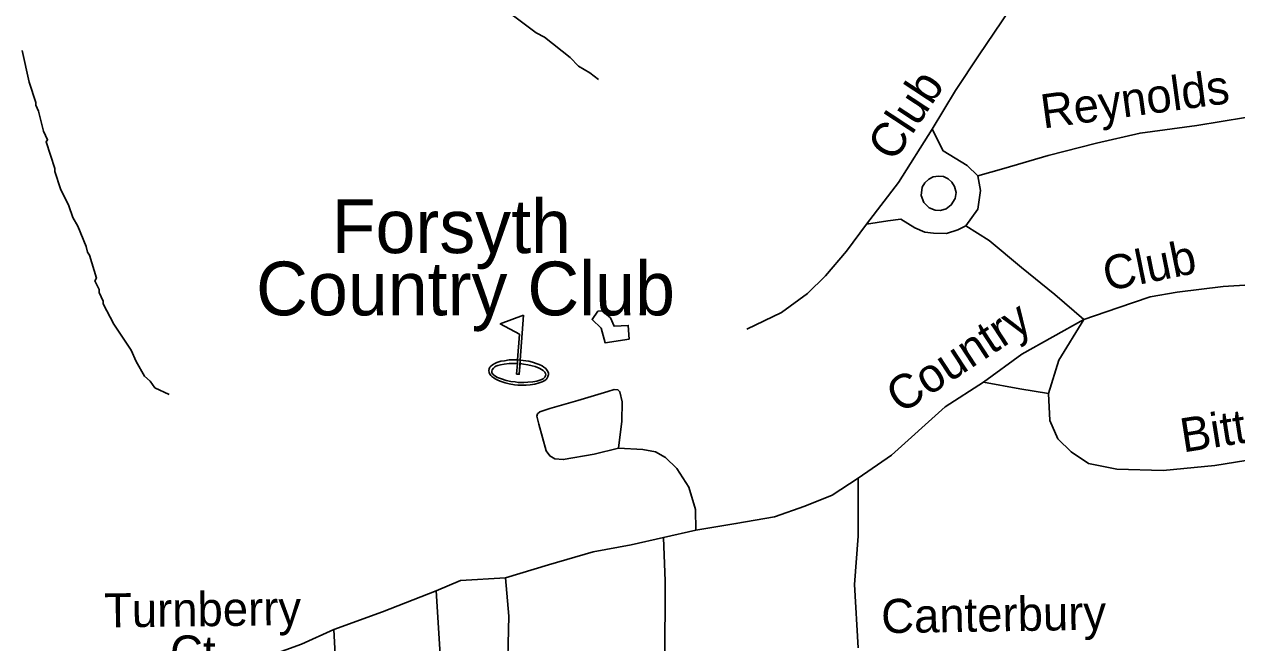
# Model space of a CAD drawing. Extents: x 1547597 to 1699558, y 810033 to 920809.
# Drawn here: x 1614630 to 1618018, y 856716 to 858442 of the extents above; entities that cross this region are included whole.
import ezdxf

# ---------------------------------------------------------------- set-up
doc = ezdxf.new("R2010")
doc.units = 0
for name, color, linetype in [('Exist Cultural Recreational Golf Course CELL', 7, 'Continuous'), ('Exist Cultural Recreational Golf Course Label', 7, 'Continuous'), ('Exist Hydrographic Misc Water Feature', 7, 'Continuous'), ('Exist Road Non-System Type 51', 7, 'Continuous'), ('Exist Road Non-System Type 51 Label', 7, 'Continuous')]:
    doc.layers.add(name, color=color, linetype=linetype)

msp = doc.modelspace()

# ---------------------------------------------------------------- linework, layer by layer
at = {"layer": 'Exist Cultural Recreational Golf Course CELL'}
msp.add_lwpolyline([(1616025.6, 857630), (1615960.2, 857605.4), (1616014.3, 857576.7), (1616009, 857505.3), (1616016.3, 857504.8), (1616015.6, 857494.8), (1616013.4, 857464.9), (1616015.6, 857494.8), (1616025, 857493.5), (1616037.1, 857491.3), (1616049.5, 857488.7), (1616057.8, 857486.4), (1616068.7, 857482.2), (1616071.4, 857481.2), (1616080.1, 857475.8), (1616084.6, 857471.1), (1616086.5, 857467.1), (1616087.4, 857463.2), (1616087.1, 857461.5), (1616086.6, 857459.9), (1616086.1, 857458.6), (1616085.1, 857457.2), (1616080.5, 857452.7), (1616073.9, 857449.4), (1616062.7, 857446.1), (1616051.9, 857443.9), (1616037.6, 857442.7), (1616026.7, 857441.9), (1616010.6, 857442.4), (1616001.7, 857443.8), (1615990.2, 857445.2), (1615977.1, 857448), (1615963.8, 857452), (1615952.4, 857456.3), (1615944.9, 857460.2), (1615940.4, 857464.4), (1615937.3, 857469.4), (1615936.6, 857473.5), (1615938, 857477.8), (1615941.1, 857482), (1615944.8, 857485.6), (1615948.5, 857487.4), (1615953.3, 857489.3), (1615961.1, 857491.4), (1615971.7, 857493.4), (1615985, 857494.8), (1615997.9, 857495.5), (1616008.2, 857495.3), (1616009, 857505.3), (1616016.3, 857504.8), (1616013.4, 857464.9), (1616006, 857465.4), (1616008.2, 857495.3), (1616009, 857505.3), (1615992.7, 857505), (1615984.9, 857504.9), (1615972.4, 857502.9), (1615962, 857501.2), (1615950.4, 857497.6), (1615945.3, 857495.2), (1615938.7, 857491.7), (1615934.3, 857487.6), (1615931.5, 857484.5), (1615929.6, 857479.8), (1615928.9, 857475.9), (1615929.5, 857470), (1615930.4, 857467.1), (1615933.7, 857462), (1615936.8, 857458.9), (1615942, 857454.7), (1615946.5, 857452), (1615955.2, 857447.6), (1615962.6, 857445), (1615974.5, 857441.2), (1615985.5, 857438.2), (1615999.9, 857435.8), (1616009.3, 857434.7), (1616022.8, 857434.5), (1616033, 857434.7), (1616043.6, 857435.8), (1616056.6, 857437.4), (1616069.3, 857440.7), (1616077.3, 857444.1), (1616085.1, 857448), (1616089.2, 857451.7), (1616091.9, 857454.9), (1616093.1, 857457), (1616093.8, 857458.6), (1616094.5, 857461.1), (1616095.1, 857463.8), (1616094.8, 857468.3), (1616093.3, 857472.5), (1616089.7, 857477.9), (1616087.4, 857480.7), (1616081.8, 857485.1), (1616077.3, 857488.1), (1616069.3, 857492.1), (1616063.7, 857494.2), (1616050.8, 857498.6), (1616040, 857501.4), (1616016.3, 857504.8)], close=True, dxfattribs=at)
at = {"layer": 'Exist Hydrographic Misc Water Feature'}
for points in [[(1616234.8, 858288), (1616211, 858306.3), (1616179.3, 858324.7), (1616155.6, 858349), (1616084.5, 858406.1), (1616060.6, 858418.4), (1615997.3, 858465.3), (1615981.4, 858473.5), (1615847, 858583.3), (1615823.2, 858599.7), (1615807.3, 858605.9), (1615736.2, 858668.9), (1615672.9, 858717.7), (1615649.1, 858730), (1615625.4, 858750.4), (1615585.8, 858774.9), (1615536.4, 858817.6), (1615491, 858868.2), (1615467.4, 858884.5), (1615443.7, 858908.9), (1615427.8, 858921.1), (1615380.9, 858945.4)], [(1615035.4, 857408.9), (1614995.6, 857427.5), (1614981.9, 857445.6), (1614966.1, 857459.9), (1614942.7, 857500.2), (1614929.1, 857532.4), (1614880.2, 857605.1), (1614851, 857661.5), (1614851.1, 857669.5), (1614839.4, 857693.6), (1614839.5, 857701.6), (1614827.8, 857725.7), (1614831.9, 857733.7), (1614812.8, 857797.9), (1614807, 857806), (1614803.2, 857822.1), (1614779.9, 857878.4), (1614766.3, 857902.5), (1614754.7, 857934.7), (1614731.4, 857983), (1614716.1, 858031.3), (1614716.2, 858039.3), (1614691.2, 858113.6), (1614695.3, 858119.5), (1614683.7, 858143.7), (1614670.4, 858199.8), (1614662.6, 858216), (1614662.7, 858224), (1614643.6, 858280.2), (1614624.7, 858368.4)], [(1616320.4, 857562.6), (1616253.1, 857553.1), (1616242.3, 857593.8), (1616216.9, 857617.9), (1616233.2, 857641.1), (1616245.3, 857642), (1616268.8, 857622.4), (1616278.4, 857598.9), (1616317.9, 857601.4), (1616320.4, 857562.6)]]:
    msp.add_lwpolyline(points, dxfattribs=at)
at = {"layer": 'Exist Road Non-System Type 51'}
for p, q in [((1616506.7, 857030.1), (1616416.5, 857009.7)), ((1615780.9, 856860.9), (1615814.7, 856351.8))]:
    msp.add_line(p, q, dxfattribs=at)
for points in [[(1617621.6, 858847.1), (1617547.6, 858734.7), (1617424.9, 858544.7), (1617298.6, 858356.8), (1617232.8, 858257), (1617167.1, 858148.7)], [(1617295.2, 858019), (1617367.4, 858039.8), (1617491.8, 858075.9), (1617626.2, 858110), (1617748.4, 858138.1), (1617906.6, 858159.7), (1618042.7, 858181.6), (1618168.9, 858197.8), (1618290.4, 858208.4)], [(1617167.1, 858148.7), (1617073.1, 858000.3), (1616983.5, 857883.7)], [(1617295.2, 858019), (1617265.5, 858047.5), (1617198.3, 858088.4), (1617167.1, 858148.7)], [(1617146.9, 857999.2), (1617157.9, 858010), (1617169.9, 858016.2), (1617184.7, 858018.3), (1617198.7, 858016.6), (1617211.6, 858010.7), (1617222.2, 858000.9), (1617229.8, 857989.4), (1617234, 857972.3), (1617231.5, 857955.7), (1617220.5, 857937.7), (1617206.3, 857926.8), (1617191, 857922.5), (1617175.6, 857922.8), (1617158.5, 857930), (1617144.2, 857944.5), (1617136.8, 857964.2), (1617139.5, 857987.4), (1617146.9, 857999.2)], [(1617261.1, 857879.5), (1617295.1, 857926.2), (1617302, 857977.9), (1617295.2, 858019)], [(1616983.5, 857883.7), (1616928.3, 857808.6), (1616869.3, 857739.5), (1616818.7, 857690.3), (1616746, 857637.4), (1616649.4, 857590.9)], [(1616983.5, 857883.7), (1617043.5, 857892.9), (1617079.6, 857898.3), (1617119.1, 857873.7), (1617146.9, 857861.4), (1617170.9, 857858.9), (1617206.9, 857858.3), (1617238.9, 857867.9), (1617261.1, 857879.5)], [(1617261.1, 857879.5), (1617326.3, 857838.5), (1617417.1, 857763.2), (1617510, 857687.9), (1617591.2, 857618.2)], [(1618396.4, 857735), (1618206.5, 857724), (1617980.5, 857709.8), (1617852.3, 857694), (1617776.2, 857681.1), (1617685.7, 857650.7), (1617591.2, 857618.2)], [(1617591.2, 857618.2), (1617418, 857521.1), (1617310.7, 857442.8)], [(1617492.4, 857411.3), (1617521.1, 857504.2), (1617591.2, 857618.2)], [(1617310.7, 857442.8), (1617203.7, 857374.5), (1617053.6, 857239.1), (1616960.7, 857174.8)], [(1617492.4, 857411.3), (1617412.6, 857424.5), (1617310.7, 857442.8)], [(1616290.6, 857258.4), (1616222.4, 857241.6), (1616136.5, 857226.7), (1616112.5, 857229.2), (1616098.7, 857237.3), (1616088.8, 857251.5), (1616068.1, 857325.7), (1616062.3, 857347.9), (1616064.3, 857354.4), (1616070.6, 857359.7), (1616098.6, 857369.3), (1616176.9, 857392.2), (1616261.2, 857416.9), (1616279.1, 857422.5), (1616289.1, 857421.9), (1616295, 857416.4), (1616300.7, 857388.3), (1616299.8, 857334.2), (1616290.6, 857258.4)], [(1618407.4, 857277.7), (1618341.4, 857272.8), (1618165.1, 857243.4), (1617956.8, 857210.6), (1617812.8, 857196.7), (1617683, 857200.5), (1617604.5, 857215.9), (1617555.7, 857248.5), (1617518.4, 857285.1), (1617496.4, 857336), (1617492.4, 857411.3)], [(1616506.7, 857030.1), (1616505.9, 857087.3), (1616486.9, 857149.6), (1616453.8, 857202.1), (1616422.2, 857232.5), (1616394.5, 857248.9), (1616358.6, 857255.4), (1616290.6, 857258.4)], [(1616960.7, 857174.8), (1616887.9, 857127.8), (1616811.4, 857097.1), (1616727.2, 857066.6), (1616618.9, 857048.4), (1616506.7, 857030.1)], [(1616960.7, 857174.8), (1616960.8, 857013.5), (1616950.7, 856877.8), (1616960.1, 856701.7)], [(1616416.5, 857009.7), (1616326.2, 856989.1), (1616219.9, 856968.9), (1616095.5, 856933), (1615975.1, 856897)], [(1616416.5, 857009.7), (1616421.4, 856887.7), (1616420, 856659.8), (1616416.3, 856420), (1616409, 856200.2), (1616406, 856002.4), (1616400.5, 855770.7), (1616386.6, 855634.9)], [(1615975.1, 856897), (1615849.2, 856888.9), (1615780.9, 856860.9)], [(1615979.4, 856116.6), (1615981.4, 856198.7), (1615978.4, 856398.6), (1615979.4, 856596.3), (1615984.4, 856790.1), (1615975.1, 856897)], [(1615780.9, 856860.9), (1615631.8, 856801.8), (1615495.1, 856752.1)], [(1615495.1, 856752.1), (1615405.1, 856711.7), (1615283.9, 856668.2)], [(1615495.1, 856752.1), (1615507.6, 856522.1), (1615510.7, 856397.8)]]:
    msp.add_lwpolyline(points, dxfattribs=at)

# ---------------------------------------------------------------- texts
at = {"layer": 'Exist Cultural Recreational Golf Course Label'}
for s, p in [('Forsyth', (1615489.3, 857803.2)), ('Country Club', (1615278.1, 857629.5))]:
    msp.add_text(s, height=150, rotation=0, dxfattribs=at).set_placement(p)
at = {"layer": 'Exist Road Non-System Type 51 Label'}
for s, rotation, p in [('Club', 56.6611, (1617060.4, 858054.4)), ('Reynolds', 7.7813, (1617477.5, 858150.8)), ('Club', 11.5111, (1617655.3, 857696.7)), ('Country', 33.1889, (1617079.7, 857352.6)), ('Bitting', 8.9433, (1617868.6, 857246.5)), ('Turnberry', 0.7034, (1614853.8, 856758.2)), ('Canterbury', 0.9238, (1617025.6, 856742.2)), ('Ct.', 359.6883, (1615037.5, 856641.2))]:
    msp.add_text(s, height=95, rotation=rotation, dxfattribs=at).set_placement(p)

doc.saveas('drawing.dxf')
